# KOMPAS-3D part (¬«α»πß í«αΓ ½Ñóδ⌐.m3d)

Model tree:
1. Эскиз:2
2. Операция выдавливания:1
     Расстояние 1 = 196.7; Расстояние 2 = 109.5
3. Смещенная плоскость:1
     Расстояние = 68.3
4. Эскиз:3
5. Операция выдавливания:2
     Расстояние 1 = 160; Расстояние 2 = 12.2
6. Эскиз:4
7. Вырезать элемент выдавливания:1
     Расстояние 1 = 300.7
8. Эскиз:6
9. Операция выдавливания:3
     Расстояние 1 = 89.3; Расстояние 2 = 12
10. Эскиз:50
11. Операция выдавливания:25
     Расстояние 1 = 2; Расстояние 2 = 2
12. Эскиз:52
13. Вырезать элемент выдавливания:22
     Расстояние 1 = 12.2
14. Эскиз:53
15. Вырезать элемент выдавливания:23
     Расстояние 1 = 12.2
16. Эскиз:54
17. Вырезать элемент выдавливания:24
     Расстояние 1 = 12.2
18. Эскиз:56
19. Вырезать элемент выдавливания:25
     Расстояние 1 = 0.7
20. Эскиз:62
21. Операция выдавливания:29
     Расстояние 1 = 160; Расстояние 2 = 12.2
22. Эскиз:63
23. Вырезать элемент выдавливания:30
     Расстояние 1 = 12.2
24. Эскиз:67
25. Вырезать элемент выдавливания:33
     Расстояние 1 = 12.2
26. Эскиз:73
27. Операция выдавливания:31
     Расстояние 1 = 196.7; Расстояние 2 = 9
28. Эскиз:74
29. Вырезать элемент выдавливания:39
     Расстояние 1 = 1.5
30. Эскиз:85
31. Вырезать элемент выдавливания:41
     Расстояние 1 = 11.6856
32. Эскиз:86
33. Вырезать элемент выдавливания:42
     Расстояние 2 = 0.514358; Расстояние 1 = 11.6856
34. Эскиз:88
35. Вырезать элемент выдавливания:44
     Расстояние 1 = 0.5
36. Эскиз:89
37. Вырезать элемент выдавливания:45
     Расстояние 1 = 8.87623
38. Эскиз:90
39. Вырезать элемент выдавливания:46
     Расстояние 1 = 11.6856
40. Вырезать элемент выдавливания:47
     Расстояние 1 = 12.2
41. Эскиз:92
42. Вырезать элемент выдавливания:48
     Расстояние 1 = 11.6856
43. Эскиз:93
44. Вырезать элемент выдавливания:49
     Расстояние 1 = 300.693
45. Скругление:1
     Радиус = 2
46. Скругление:2
     Радиус = 0.3
47. Скругление:3
     Радиус = 0.3
48. Скругление:4
     Радиус = 0.1
49. Скругление:5
     Радиус = 1
50. Скругление:6
     Радиус = 2
51. Скругление:7
     Радиус = 2
52. Скругление:8
     Радиус = 0.1
53. Скругление:9
     Радиус = 0.1
54. Скругление:10
     Радиус = 0.1

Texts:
  корпус борт левый
  Сплав АЛ8  ГОСТ 1583-93
  stalker61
